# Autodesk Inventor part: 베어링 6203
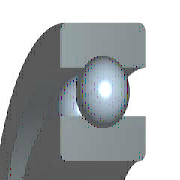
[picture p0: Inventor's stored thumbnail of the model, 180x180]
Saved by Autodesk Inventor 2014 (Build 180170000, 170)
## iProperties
IsCustomPart: 0
Created: 2016-04
Part Number: 베어링 6203
Material: 강철, 연강
Description: 깊은 그루브 볼 베어링
Document SubType Name: Modeling
Standard: KS B 2023
Designer: mdu
Standards Organization: KS
Language: ko-KR
Size Designation: 6203 - 17 x 40 x 12
Categories: <MemberInstance><Categories><Category DisplayName="샤프트 부품" InternalName="7f7aeb1f-a693-4053-b835-cee3144e0d98" Mnemonic="SHFT"><Category DisplayName="베어링" Inter
Density: 7.86 g/cm^3
Mass: 64.9809 g
Surface Area: 64.3582 cm^2
Volume: 8.26729 cm^3
Appearance: 노란색
Author: mdu
Revision Number: 1
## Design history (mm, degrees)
sketch "스케치" dims "d0" = 5.98 (= -0.26 x WD + 0.26 x BD)
  geometry: L1 (3.01, 14.25)-(8.99, 14.25); L2 (6, 14.25)-(6, 11.26); L3 (6, 14.25)-(6, 17.24); L4 (3.778, 12.249)-(0, 12.249); L5 (0, 8.5)-(12, 8.5); L6 (3.778, 16.251)-(0, 16.251); L7 (0, 20)-(12, 20); L8 (12, 8.5)-(12, 12.249); L9 (8.222, 12.249)-(12, 12.249); L10 (8.222, 16.251)-(12, 16.251); L11 (12, 20)-(12, 16.251); L12 (-1.4, 0)-(8.4, 0) reference; L13 (0, -0.3)-(0, 5.3) reference
  constraints: 22 end point, 4 point on line, 2 collinear, 2 perpendicular, 2 symmetric about line, 1 midpoint, 1 parallel, 14 other
  dimensions: "d9" = 17 diameter of L5 L12 (= WD); "d11" = 40 diameter of L7 L12 (= BD); "d12" = 12 distance between parallel lines of L8 L13 (= KB); "d13" = 24.498 diameter of L9 L12 (= 0.326 x BD + 0.674 x WD)
revolve "본체" stored, may be unused: angle "d6" = 90 deg
revolve "볼" stored, may be unused: angle "d7" = 90 deg
pattern_circular "IDS_ARRAYBALL[SIMPL:T]" dims angle "d3" = 360 deg
body "Solid1"
fillet "모깎기1" dims "d1" = 0.6 (= KRS)
other parameters: "WD" = 17 [user parameter; used in 5 equation terms], "BD" = 40 [user parameter; used in 5 equation terms], "KB" = 12 [user parameter; used in 1 equation term], "KRS" = 0.6 [user parameter; used in 1 equation term], "d4" = 0, "d5" = 0, "d8" = 0, "d14" = 0, "d15" = 0, "BBA" = 0 [user parameter], "BC0" = 4750000 [user parameter], "BC" = 9560000 [user parameter], "WR" = 8.5 (= 0.5 x WD) [user parameter]
